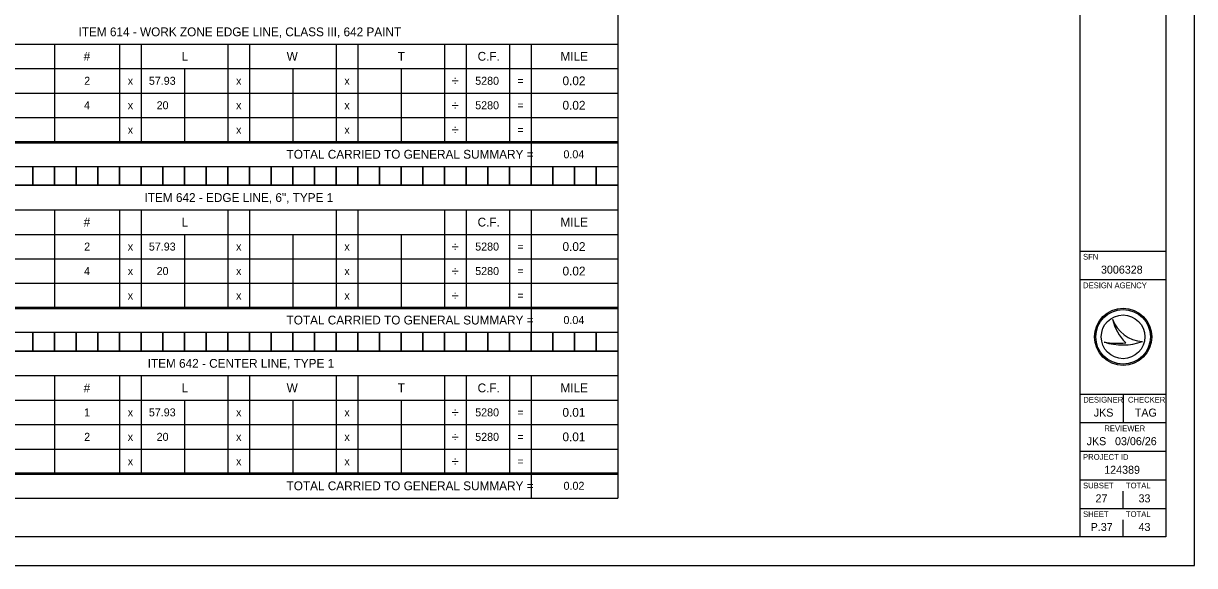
# Model space of a CAD drawing. Extents: x 0 to 34, y 0 to 22.
# Drawn here: x 13.52 to 34, y 0 to 9.48 of the extents above; entities that cross this region are included whole.
import ezdxf

# ---------------------------------------------------------------- set-up
doc = ezdxf.new("R2010")
doc.units = 0
for name, color, linetype in [('Default', 7, 'Continuous'), ('SH_Border', 7, 'Continuous'), ('SH_Cut_Line', 7, 'Continuous'), ('SH_Data', 7, 'Continuous')]:
    doc.layers.add(name, color=color, linetype=linetype)

msp = doc.modelspace()

# ---------------------------------------------------------------- linework, layer by layer
at = {"layer": 'Default'}
for p, q in [((23.913, 10.316), (23.913, 7.395)), ((10.654, 9.119), (23.913, 9.119)), ((14.063, 9.119), (14.063, 7.417)), ((15.2, 9.119), (15.2, 7.417)), ((15.578, 9.119), (15.578, 7.417)), ((17.094, 9.119), (17.094, 7.417)), ((17.472, 9.119), (17.472, 7.417)), ((18.988, 9.119), (18.988, 7.417)), ((19.367, 9.119), (19.367, 7.417)), ((20.882, 9.119), (20.882, 7.417)), ((21.261, 9.119), (21.261, 7.417)), ((22.018, 9.119), (22.018, 7.417)), ((22.397, 9.119), (22.397, 7.417)), ((10.654, 8.691), (23.913, 8.691)), ((16.336, 8.691), (16.336, 7.417)), ((18.23, 8.691), (18.23, 7.417)), ((20.124, 8.691), (20.124, 7.417)), ((10.654, 8.263), (23.913, 8.263)), ((10.654, 7.835), (23.913, 7.835)), ((10.654, 7.417), (23.913, 7.417)), ((10.654, 7.395), (23.913, 7.395)), ((22.397, 7.395), (22.397, 6.978)), ((23.913, 7.417), (23.913, 4.497)), ((10.654, 6.978), (23.913, 6.978)), ((10.654, 6.649), (23.913, 6.649)), ((10.654, 6.22), (23.913, 6.22)), ((14.063, 6.22), (14.063, 4.518)), ((15.2, 6.22), (15.2, 4.518)), ((15.578, 6.22), (15.578, 4.518)), ((17.094, 6.22), (17.094, 4.518)), ((17.472, 6.22), (17.472, 4.518)), ((18.988, 6.22), (18.988, 4.518)), ((19.367, 6.22), (19.367, 4.518)), ((20.882, 6.22), (20.882, 4.518)), ((21.261, 6.22), (21.261, 4.518)), ((22.018, 6.22), (22.018, 4.518)), ((22.397, 6.22), (22.397, 4.518)), ((10.654, 5.792), (23.913, 5.792)), ((16.336, 5.792), (16.336, 4.518)), ((18.23, 5.792), (18.23, 4.518)), ((20.124, 5.792), (20.124, 4.518)), ((10.654, 5.364), (23.913, 5.364)), ((10.654, 4.936), (23.913, 4.936)), ((10.654, 4.518), (23.913, 4.518)), ((23.913, 4.518), (23.913, 1.598)), ((10.654, 4.497), (23.913, 4.497)), ((22.397, 4.497), (22.397, 4.079)), ((10.654, 4.079), (23.913, 4.079)), ((10.654, 3.75), (23.913, 3.75)), ((10.654, 3.322), (23.913, 3.322)), ((14.063, 3.322), (14.063, 1.62)), ((15.2, 3.322), (15.2, 1.62)), ((15.578, 3.322), (15.578, 1.62)), ((17.094, 3.322), (17.094, 1.62)), ((17.472, 3.322), (17.472, 1.62)), ((18.988, 3.322), (18.988, 1.62)), ((19.367, 3.322), (19.367, 1.62)), ((20.882, 3.322), (20.882, 1.62)), ((21.261, 3.322), (21.261, 1.62)), ((22.018, 3.322), (22.018, 1.62)), ((22.397, 3.322), (22.397, 1.62)), ((10.654, 2.893), (23.913, 2.893)), ((16.336, 2.893), (16.336, 1.62)), ((18.23, 2.893), (18.23, 1.62)), ((20.124, 2.893), (20.124, 1.62)), ((10.654, 2.465), (23.913, 2.465)), ((10.654, 2.037), (23.913, 2.037)), ((10.654, 1.62), (23.913, 1.62)), ((10.654, 1.598), (23.913, 1.598)), ((22.397, 1.598), (22.397, 1.18)), ((23.913, 1.62), (23.913, 1.18)), ((10.654, 1.18), (23.913, 1.18))]:
    msp.add_line(p, q, dxfattribs=at)
for points in [[(13.305, 6.978), (13.684, 6.978), (13.684, 6.649), (13.305, 6.649)], [(13.684, 6.978), (14.063, 6.978), (14.063, 6.649), (13.684, 6.649)], [(14.063, 6.978), (14.442, 6.978), (14.442, 6.649), (14.063, 6.649)], [(14.442, 6.978), (14.821, 6.978), (14.821, 6.649), (14.442, 6.649)], [(14.821, 6.978), (15.2, 6.978), (15.2, 6.649), (14.821, 6.649)], [(15.2, 6.978), (15.578, 6.978), (15.578, 6.649), (15.2, 6.649)], [(15.578, 6.978), (15.957, 6.978), (15.957, 6.649), (15.578, 6.649)], [(15.957, 6.978), (16.336, 6.978), (16.336, 6.649), (15.957, 6.649)], [(16.336, 6.978), (16.715, 6.978), (16.715, 6.649), (16.336, 6.649)], [(16.715, 6.978), (17.094, 6.978), (17.094, 6.649), (16.715, 6.649)], [(17.094, 6.978), (17.472, 6.978), (17.472, 6.649), (17.094, 6.649)], [(17.472, 6.978), (17.851, 6.978), (17.851, 6.649), (17.472, 6.649)], [(17.851, 6.978), (18.23, 6.978), (18.23, 6.649), (17.851, 6.649)], [(18.23, 6.978), (18.609, 6.978), (18.609, 6.649), (18.23, 6.649)], [(18.609, 6.978), (18.988, 6.978), (18.988, 6.649), (18.609, 6.649)], [(18.988, 6.978), (19.367, 6.978), (19.367, 6.649), (18.988, 6.649)], [(19.367, 6.978), (19.745, 6.978), (19.745, 6.649), (19.367, 6.649)], [(19.745, 6.978), (20.124, 6.978), (20.124, 6.649), (19.745, 6.649)], [(20.124, 6.978), (20.503, 6.978), (20.503, 6.649), (20.124, 6.649)], [(20.503, 6.978), (20.882, 6.978), (20.882, 6.649), (20.503, 6.649)], [(20.882, 6.978), (21.261, 6.978), (21.261, 6.649), (20.882, 6.649)], [(21.261, 6.978), (21.64, 6.978), (21.64, 6.649), (21.261, 6.649)], [(21.64, 6.978), (22.018, 6.978), (22.018, 6.649), (21.64, 6.649)], [(22.018, 6.978), (22.397, 6.978), (22.397, 6.649), (22.018, 6.649)], [(22.397, 6.978), (22.776, 6.978), (22.776, 6.649), (22.397, 6.649)], [(22.776, 6.978), (23.155, 6.978), (23.155, 6.649), (22.776, 6.649)], [(23.155, 6.978), (23.534, 6.978), (23.534, 6.649), (23.155, 6.649)], [(23.534, 6.978), (23.913, 6.978), (23.913, 6.649), (23.534, 6.649)], [(13.305, 4.079), (13.684, 4.079), (13.684, 3.75), (13.305, 3.75)], [(13.684, 4.079), (14.063, 4.079), (14.063, 3.75), (13.684, 3.75)], [(14.063, 4.079), (14.442, 4.079), (14.442, 3.75), (14.063, 3.75)], [(14.442, 4.079), (14.821, 4.079), (14.821, 3.75), (14.442, 3.75)], [(14.821, 4.079), (15.2, 4.079), (15.2, 3.75), (14.821, 3.75)], [(15.2, 4.079), (15.578, 4.079), (15.578, 3.75), (15.2, 3.75)], [(15.578, 4.079), (15.957, 4.079), (15.957, 3.75), (15.578, 3.75)], [(15.957, 4.079), (16.336, 4.079), (16.336, 3.75), (15.957, 3.75)], [(16.336, 4.079), (16.715, 4.079), (16.715, 3.75), (16.336, 3.75)], [(16.715, 4.079), (17.094, 4.079), (17.094, 3.75), (16.715, 3.75)], [(17.094, 4.079), (17.472, 4.079), (17.472, 3.75), (17.094, 3.75)], [(17.472, 4.079), (17.851, 4.079), (17.851, 3.75), (17.472, 3.75)], [(17.851, 4.079), (18.23, 4.079), (18.23, 3.75), (17.851, 3.75)], [(18.23, 4.079), (18.609, 4.079), (18.609, 3.75), (18.23, 3.75)], [(18.609, 4.079), (18.988, 4.079), (18.988, 3.75), (18.609, 3.75)], [(18.988, 4.079), (19.367, 4.079), (19.367, 3.75), (18.988, 3.75)], [(19.367, 4.079), (19.745, 4.079), (19.745, 3.75), (19.367, 3.75)], [(19.745, 4.079), (20.124, 4.079), (20.124, 3.75), (19.745, 3.75)], [(20.124, 4.079), (20.503, 4.079), (20.503, 3.75), (20.124, 3.75)], [(20.503, 4.079), (20.882, 4.079), (20.882, 3.75), (20.503, 3.75)], [(20.882, 4.079), (21.261, 4.079), (21.261, 3.75), (20.882, 3.75)], [(21.261, 4.079), (21.64, 4.079), (21.64, 3.75), (21.261, 3.75)], [(21.64, 4.079), (22.018, 4.079), (22.018, 3.75), (21.64, 3.75)], [(22.018, 4.079), (22.397, 4.079), (22.397, 3.75), (22.018, 3.75)], [(22.397, 4.079), (22.776, 4.079), (22.776, 3.75), (22.397, 3.75)], [(22.776, 4.079), (23.155, 4.079), (23.155, 3.75), (22.776, 3.75)], [(23.155, 4.079), (23.534, 4.079), (23.534, 3.75), (23.155, 3.75)], [(23.534, 4.079), (23.913, 4.079), (23.913, 3.75), (23.534, 3.75)]]:
    msp.add_lwpolyline(points, close=True, dxfattribs=at)
at = {"layer": 'SH_Border'}
for p, q in [((32, 0.5), (32, 21.5)), ((32, 5.5), (33.5, 5.5)), ((32, 5), (33.5, 5)), ((32, 3), (33.5, 3)), ((32.75, 3), (32.75, 2.5)), ((32, 2.5), (33.5, 2.5)), ((32, 2), (33.5, 2)), ((32, 1.5), (33.5, 1.5)), ((32, 1), (33.5, 1))]:
    msp.add_line(p, q, dxfattribs=at)
msp.add_lwpolyline([(1.5, 21.5), (33.5, 21.5), (33.5, 0.5), (1.5, 0.5)], close=True, dxfattribs=at)
at = {"layer": 'SH_Cut_Line'}
msp.add_lwpolyline([(0, 0), (34, 0), (34, 22), (0, 22)], close=True, dxfattribs=at)
at = {"layer": 'SH_Data'}
for p, q in [((32.567, 4.31), (32.567, 4.31)), ((32.417, 3.91), (32.417, 3.91)), ((32.75, 4), (32.75, 4)), ((33.087, 3.919), (33.087, 3.919)), ((32.75, 1), (32.75, 1.3)), ((32.375, 0.675), (32.375, 0.675)), ((32.75, 0.5), (32.75, 0.8))]:
    msp.add_line(p, q, dxfattribs=at)
for radius in [0.5, 0.477, 0.477, 0.382]:
    msp.add_circle((32.75, 4), radius, dxfattribs=at)
for centre, radius, start, end in [((33.116, 4.498), 0.58, 198.9257, 198.9319), ((33.347, 4.47), 0.796, 191.6379, 191.6421), ((33.116, 4.498), 0.58, 198.9319, 267.1657), ((33.347, 4.47), 0.796, 191.6421, 226.0947), ((32.739, 4.87), 1.013, 251.4576, 290.0832), ((32.648, 5.154), 1.266, 259.4964, 259.4995), ((32.739, 4.87), 1.013, 251.4527, 251.4576), ((32.648, 5.154), 1.266, 259.4995, 276.6672)]:
    msp.add_arc(centre, radius, start, end, dxfattribs=at)

# ---------------------------------------------------------------- texts
at = {"layer": 'Default'}
for s, height, p in [('ITEM 614 - WORK ZONE EDGE LINE, CLASS III, 642 PAINT', 0.154, (14.483, 9.256)), ('#', 0.154, (14.573, 8.828)), ('L', 0.154, (16.285, 8.828)), ('W', 0.154, (18.123, 8.828)), ('T', 0.154, (20.065, 8.828)), ('C.F.', 0.154, (21.462, 8.828)), ('MILE', 0.154, (22.911, 8.828)), ('2', 0.14, (14.582, 8.407)), ('x', 0.14, (15.344, 8.407)), ('57.93', 0.14, (15.713, 8.407)), ('x', 0.14, (17.238, 8.407)), ('x', 0.14, (19.132, 8.407)), ('÷', 0.168, (21.009, 8.393)), ('5280', 0.14, (21.42, 8.407)), ('=', 0.14, (22.158, 8.407)), ('0.02', 0.154, (22.947, 8.4)), ('4', 0.14, (14.579, 7.979)), ('x', 0.14, (15.344, 7.979)), ('20', 0.14, (15.849, 7.979)), ('x', 0.14, (17.238, 7.979)), ('x', 0.14, (19.132, 7.979)), ('÷', 0.168, (21.009, 7.965)), ('5280', 0.14, (21.42, 7.979)), ('=', 0.14, (22.158, 7.979)), ('0.02', 0.154, (22.947, 7.972)), ('x', 0.14, (15.344, 7.55)), ('x', 0.14, (17.238, 7.55)), ('x', 0.14, (19.132, 7.55)), ('÷', 0.168, (21.009, 7.536)), ('=', 0.14, (22.158, 7.55)), ('TOTAL CARRIED TO GENERAL SUMMARY =', 0.154, (18.121, 7.115)), ('0.04', 0.14, (22.963, 7.122)), ('ITEM 642 - EDGE LINE, 6", TYPE 1', 0.154, (15.637, 6.358)), ('#', 0.154, (14.573, 5.929)), ('L', 0.154, (16.285, 5.929)), ('C.F.', 0.154, (21.462, 5.929)), ('MILE', 0.154, (22.911, 5.929)), ('2', 0.14, (14.582, 5.508)), ('x', 0.14, (15.344, 5.508)), ('57.93', 0.14, (15.713, 5.508)), ('x', 0.14, (17.238, 5.508)), ('x', 0.14, (19.132, 5.508)), ('÷', 0.168, (21.009, 5.494)), ('5280', 0.14, (21.42, 5.508)), ('=', 0.14, (22.158, 5.508)), ('0.02', 0.154, (22.947, 5.501)), ('4', 0.14, (14.579, 5.08)), ('x', 0.14, (15.344, 5.08)), ('20', 0.14, (15.849, 5.08)), ('x', 0.14, (17.238, 5.08)), ('x', 0.14, (19.132, 5.08)), ('÷', 0.168, (21.009, 5.066)), ('5280', 0.14, (21.42, 5.08)), ('=', 0.14, (22.158, 5.08)), ('0.02', 0.154, (22.947, 5.073)), ('x', 0.14, (15.344, 4.652)), ('x', 0.14, (17.238, 4.652)), ('x', 0.14, (19.132, 4.652)), ('÷', 0.168, (21.009, 4.638)), ('=', 0.14, (22.158, 4.652)), ('TOTAL CARRIED TO GENERAL SUMMARY =', 0.154, (18.121, 4.216)), ('0.04', 0.14, (22.963, 4.223)), ('ITEM 642 - CENTER LINE, TYPE 1', 0.154, (15.692, 3.459)), ('#', 0.154, (14.573, 3.03)), ('L', 0.154, (16.285, 3.03)), ('W', 0.154, (18.123, 3.03)), ('T', 0.154, (20.065, 3.03)), ('C.F.', 0.154, (21.462, 3.03)), ('MILE', 0.154, (22.911, 3.03)), ('1', 0.14, (14.581, 2.609)), ('x', 0.14, (15.344, 2.609)), ('57.93', 0.14, (15.713, 2.609)), ('x', 0.14, (17.238, 2.609)), ('x', 0.14, (19.132, 2.609)), ('÷', 0.168, (21.009, 2.595)), ('5280', 0.14, (21.42, 2.609)), ('=', 0.14, (22.158, 2.609)), ('0.01', 0.154, (22.946, 2.602)), ('2', 0.14, (14.582, 2.181)), ('x', 0.14, (15.344, 2.181)), ('20', 0.14, (15.849, 2.181)), ('x', 0.14, (17.238, 2.181)), ('x', 0.14, (19.132, 2.181)), ('÷', 0.168, (21.009, 2.167)), ('5280', 0.14, (21.42, 2.181)), ('=', 0.14, (22.158, 2.181)), ('0.01', 0.154, (22.946, 2.174)), ('x', 0.14, (15.344, 1.753)), ('x', 0.14, (17.238, 1.753)), ('x', 0.14, (19.132, 1.753)), ('÷', 0.168, (21.009, 1.739)), ('=', 0.14, (22.158, 1.753)), ('TOTAL CARRIED TO GENERAL SUMMARY =', 0.154, (18.121, 1.318)), ('0.02', 0.14, (22.965, 1.325))]:
    msp.add_text(s, height=height, dxfattribs=at).set_placement(p)
at = {"layer": 'SH_Data'}
for s, height, p in [('SFN', 0.1, (32.05, 5.35)), ('3006328', 0.14, (32.363, 5.105)), ('DESIGN AGENCY', 0.1, (32.05, 4.85)), ('DESIGNER', 0.1, (32.054, 2.85)), ('CHECKER', 0.1, (32.835, 2.85)), ('JKS', 0.14, (32.237, 2.605)), ('TAG', 0.14, (32.955, 2.605)), ('REVIEWER', 0.1, (32.422, 2.35)), ('JKS', 0.14, (32.112, 2.105)), ('03/06/26', 0.14, (32.609, 2.105)), ('PROJECT ID', 0.1, (32.05, 1.85)), ('124389', 0.14, (32.42, 1.605)), ('SUBSET', 0.1, (32.05, 1.35)), ('TOTAL', 0.1, (32.8, 1.35)), ('27', 0.14, (32.268, 1.105)), ('33', 0.14, (33.02, 1.105)), ('SHEET', 0.1, (32.05, 0.85)), ('TOTAL', 0.1, (32.8, 0.85)), ('P.37', 0.14, (32.183, 0.605)), ('43', 0.14, (33.02, 0.605))]:
    msp.add_text(s, height=height, dxfattribs=at).set_placement(p)

doc.saveas('drawing.dxf')
